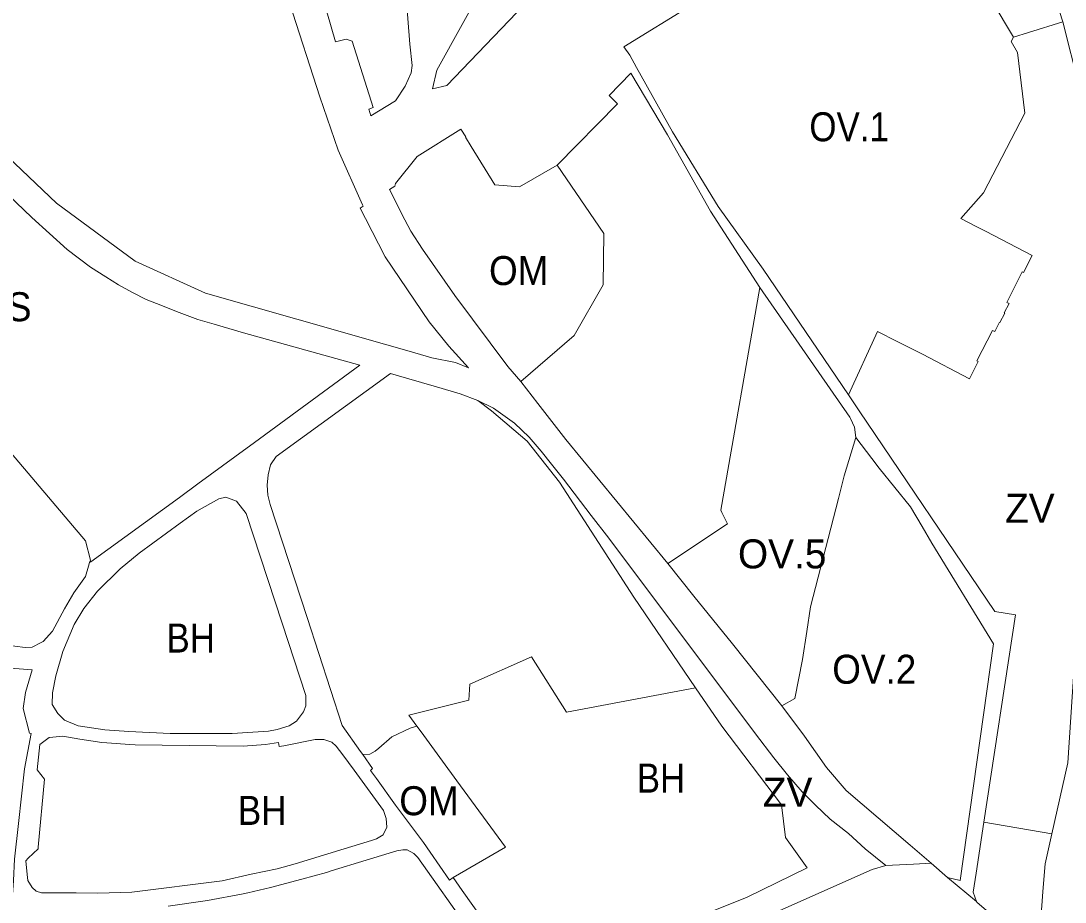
# Model space of a CAD drawing. Extents: x -650451 to -642268, y -1075216 to -1066610.
# Drawn here: x -648300.4 to -647868.5, y -1070184.8 to -1069820.3 of the extents above; entities that cross this region are included whole.
import ezdxf

# ---------------------------------------------------------------- set-up
doc = ezdxf.new("R2010")
doc.units = 0
doc.header["$LTSCALE"] = 4.8
for name, color, linetype, lineweight in [('1', 7, 'Continuous', 13), ('11', 7, 'Continuous', 13), ('12', 7, 'Continuous', 13), ('13', 7, 'Continuous', 13), ('15', 7, 'Continuous', 13), ('24', 7, 'Continuous', 13), ('25', 7, 'Continuous', 13), ('40', 7, 'Continuous', 13)]:
    doc.layers.add(name, color=color, linetype=linetype, lineweight=lineweight)
doc.layers.add('62', color=7, linetype='Continuous')

msp = doc.modelspace()

# ---------------------------------------------------------------- linework, layer by layer
at = {"layer": '1'}
for points in [[(-648395.03, -1069884.22), (-648394.65, -1069886.59), (-648395.15, -1069892.61), (-648394.35, -1069891.95), (-648373.26, -1069917.33), (-648367.49, -1069924.28), (-648364.6, -1069927.79), (-648350.48, -1069944.78), (-648341.01, -1069955.98), (-648323.69, -1069976.45), (-648316.73, -1069984.68), (-648273.67, -1070035.38), (-648271.65, -1070043.3), (-648271.95, -1070044.31)], [(-648271.95, -1070044.31), (-648271.952, -1070044.311), (-648272.42, -1070045.88), (-648273.67, -1070050.09), (-648278.48, -1070056.83), (-648282.41, -1070063.48), (-648287.34, -1070072.68), (-648291.11, -1070077.01), (-648292, -1070077.45), (-648295.66, -1070079.28), (-648298.67, -1070079.42), (-648302.91, -1070078.97), (-648311.88, -1070078.03), (-648317.52, -1070077.66), (-648327.19, -1070077.02), (-648343.29, -1070075.97), (-648350.31, -1070075.29), (-648353.76, -1070073.03), (-648359.66, -1070069.95), (-648370.54, -1070069.06), (-648388.11, -1070067.57), (-648419.45, -1070064.98), (-648446.57, -1070062.84)], [(-648136.61, -1070111.97), (-648139.91, -1070107.48), (-648115.11, -1070101.26), (-648114.7, -1070094.68), (-648089.22, -1070083.27), (-648074.76, -1070106.17), (-648021.35, -1070096.14)], [(-648021.35, -1070096.14), (-648010.55, -1070112.03), (-647985.78, -1070144.53), (-647984.1, -1070158.09), (-647975.21, -1070170.64), (-648000.23, -1070182.88), (-648016.62, -1070189.37), (-648011.68, -1070197.45)], [(-648121.6, -1070174.62), (-648099.97, -1070162.01), (-648120.06, -1070134.58), (-648125.99, -1070126.48), (-648132.7, -1070117.31), (-648133.75, -1070115.89), (-648134.45, -1070114.92), (-648136.61, -1070111.97)], [(-648239.48, -1070186.5), (-648223.26, -1070184.12), (-648208.52, -1070181.35), (-648206.53, -1070180.89), (-648197.16, -1070178.78), (-648184.18, -1070175.26), (-648174.01, -1070172.46), (-648172.09, -1070171.85), (-648157.64, -1070167.46), (-648144.96, -1070163.57), (-648142.47, -1070163.15), (-648140.61, -1070163.17), (-648137.84, -1070164.6), (-648136.17, -1070166.33), (-648114.57, -1070196.91)], [(-648011.68, -1070197.45), (-648024.97, -1070200.05), (-648029.87, -1070202.83), (-648081.95, -1070230.61), (-648084.29, -1070230.75), (-648086.84, -1070230.47), (-648089.81, -1070228.21), (-648092.22, -1070224.96), (-648097.5, -1070212.2), (-648100.3, -1070206.86), (-648104.91, -1070199.23), (-648108.41, -1070193.3), (-648117.86, -1070179.91), (-648121.6, -1070174.62)]]:
    msp.add_lwpolyline(points, dxfattribs=at)
for points in [[(-648182.51, -1070099.34), (-648182.54, -1070103.54), (-648183.54, -1070106.05), (-648186.44, -1070109.98), (-648189.4, -1070111.9), (-648194.4, -1070113.39), (-648197.98, -1070114.13), (-648212.99, -1070115.07), (-648230.77, -1070115.06), (-648233.79, -1070115), (-648238.64, -1070115), (-648255.8, -1070114.25), (-648265.64, -1070113.47), (-648276.7, -1070111.92), (-648282.33, -1070109.54), (-648285.15, -1070106.8), (-648287.42, -1070103.1), (-648287.28, -1070098.25), (-648285.93, -1070091.11), (-648283.03, -1070081.15), (-648278.31, -1070069.95), (-648274.33, -1070063.35), (-648268.73, -1070056.16), (-648259.29, -1070046.96), (-648251.42, -1070040.47), (-648234.53, -1070027.97), (-648227.66, -1070023.13), (-648218.57, -1070018.02), (-648215.61, -1070017.23), (-648211.24, -1070018.92), (-648207.15, -1070024.08), (-648192.28, -1070069.37)], [(-648150.38, -1070146.9), (-648149.31, -1070150.25), (-648149.1, -1070153.72), (-648150.59, -1070157), (-648153.26, -1070158.53), (-648155.31, -1070159.31), (-648166.7, -1070162.7), (-648186.95, -1070168.91), (-648194.4, -1070170.97), (-648205.08, -1070173.2), (-648217.18, -1070175.96), (-648254.47, -1070180.63), (-648268.56, -1070181.05), (-648277.46, -1070180.99), (-648291.84, -1070180.89), (-648294.07, -1070180.25), (-648295.72, -1070178.67), (-648297.54, -1070175.86), (-648297.81, -1070173.36), (-648298.38, -1070167.66), (-648297.44, -1070166.65), (-648293.28, -1070162.77), (-648293.22, -1070162.09), (-648290.59, -1070133.86), (-648293.6, -1070130.08), (-648292.53, -1070119.64), (-648288.71, -1070116.75), (-648284.26, -1070116.25), (-648282.99, -1070116.11), (-648275.96, -1070117.37), (-648266.95, -1070118.77), (-648264.9, -1070118.92), (-648255.26, -1070119.64), (-648253.13, -1070119.7), (-648208.45, -1070120.25), (-648199.25, -1070119.6), (-648193.81, -1070118.81), (-648193.58, -1070120.44), (-648191.62, -1070120.07), (-648178.64, -1070117.55), (-648176.49, -1070117.5), (-648175.06, -1070117.46), (-648171.75, -1070118.61), (-648169.94, -1070120.32), (-648167.26, -1070123.91), (-648162.61, -1070130.13)]]:
    msp.add_lwpolyline(points, close=True, dxfattribs=at)
at = {"layer": '11'}
for points in [[(-647958.13, -1069974.97), (-647993.37, -1069922.95), (-648011.98, -1069897.09), (-648030.85, -1069866.2), (-648045.74, -1069839.57), (-648048.56, -1069834.42), (-648051.03, -1069831.04), (-648022.75, -1069813.67), (-648017.19, -1069809.99), (-648007.72, -1069803.73), (-648002.79, -1069800.48)], [(-647898.71, -1069812.26), (-647889.83, -1069826.99)], [(-647889.83, -1069826.99), (-647890.85, -1069828.89), (-647888.27, -1069833.43), (-647885.2, -1069858.5), (-647902.22, -1069891.35), (-647911.67, -1069902.04), (-647905, -1069905.45), (-647901.47, -1069907.29), (-647882.09, -1069917.29), (-647885.73, -1069924.43), (-647886.25, -1069924.11), (-647892.61, -1069936.72), (-647891.7, -1069937.22), (-647893.68, -1069941.08), (-647893.44, -1069941.17), (-647895.45, -1069945.07), (-647895.66, -1069944.94), (-647897.64, -1069948.79), (-647898.53, -1069948.33), (-647904.96, -1069960.86), (-647904.45, -1069961.12), (-647908.08, -1069968.32), (-647927.54, -1069958.18), (-647930.53, -1069956.68), (-647937.91, -1069952.97), (-647946.07, -1069948.8), (-647958.13, -1069974.97)], [(-648032.85, -1070044.73), (-648008.18, -1070028.25), (-648010.44, -1070023.66), (-648010.94, -1070022.65), (-647994.71, -1069930.53)], [(-647994.71, -1069930.53), (-647957.59, -1069984.19), (-647957.24, -1069984.73), (-647955.65, -1069988.28), (-647955.08, -1069992.58)], [(-647955.08, -1069992.58), (-647959.84, -1070008.46), (-647962.24, -1070017.77), (-647973.82, -1070062.58), (-647975.36, -1070072.85), (-647977.13, -1070084.38), (-647980.24, -1070100.54), (-647985.64, -1070103.59)], [(-647985.64, -1070103.59), (-647980.24, -1070100.54), (-647977.13, -1070084.38), (-647975.36, -1070072.85), (-647973.82, -1070062.58), (-647962.24, -1070017.77), (-647959.84, -1070008.46), (-647955.08, -1069992.58)], [(-647955.08, -1069992.58), (-647948.506, -1070001.29), (-647948.51, -1070001.29), (-647945.48, -1070005.3), (-647932.43, -1070021.22), (-647927.6, -1070029.47), (-647923.61, -1070036.27), (-647898.15, -1070077.99), (-647911.88, -1070175.85), (-647917.1, -1070174.56), (-647923.97, -1070168.7)], [(-647985.64, -1070103.59), (-648006.05, -1070077.89), (-648022, -1070058.16), (-648032.85, -1070044.73)], [(-648379.47, -1070082.24), (-648375.71, -1070082.53), (-648358.72, -1070083.83), (-648295.75, -1070088.68), (-648298.44, -1070098.07), (-648299.4, -1070104.67), (-648296.81, -1070114.95), (-648296.09, -1070115.09), (-648298.93, -1070129.7), (-648301.38, -1070152.29), (-648302.98, -1070166.99), (-648303.45, -1070175.81), (-648304.71, -1070193.48), (-648305, -1070203.13), (-648305.26, -1070208.56)], [(-647923.97, -1070168.7), (-647932.63, -1070161.19), (-647959.1, -1070138.59), (-647967.22, -1070129.11), (-647976.36, -1070116.1), (-647985.64, -1070103.59)]]:
    msp.add_lwpolyline(points, dxfattribs=at)
at = {"layer": '12'}
for points in [[(-648093.67, -1069969.42), (-648099.05, -1069963.26), (-648120.85, -1069933.91), (-648134.34, -1069914.68), (-648139.17, -1069907.27), (-648142.86, -1069900.24), (-648147.27, -1069891.3), (-648147.87, -1069890.04), (-648145.73, -1069888.68), (-648145.5, -1069887.55), (-648136.5, -1069876.35), (-648118.4, -1069865.04), (-648116.39, -1069868.28), (-648116.48, -1069868.33), (-648114.11, -1069872.2), (-648104.4, -1069888.09), (-648094.2, -1069888.93), (-648078.54, -1069880.01)], [(-648078.54, -1069880.01), (-648059.32, -1069908.27), (-648059.5, -1069929.52), (-648071.58, -1069950.39), (-648093.67, -1069969.42)], [(-648159.02, -1070123.71), (-648156.07, -1070123.54), (-648153.85, -1070122.38), (-648152.35, -1070121.05), (-648147.02, -1070116.35), (-648139.45, -1070112.79), (-648136.61, -1070111.97)], [(-648136.61, -1070111.97), (-648134.45, -1070114.92), (-648133.75, -1070115.89), (-648132.7, -1070117.31), (-648125.99, -1070126.48), (-648120.06, -1070134.58), (-648099.97, -1070162.01), (-648121.6, -1070174.62)], [(-648121.6, -1070174.62), (-648123.08, -1070175.66), (-648131.16, -1070164.06), (-648133.91, -1070160.15), (-648145.41, -1070144.66), (-648153.3, -1070133.69), (-648155.78, -1070130.27), (-648154.95, -1070129.55), (-648159.02, -1070123.71)]]:
    msp.add_lwpolyline(points, dxfattribs=at)
at = {"layer": '13'}
msp.add_lwpolyline([(-648141.17, -1069808.61), (-648139.49, -1069829.91), (-648138.57, -1069838.78), (-648138.96, -1069841.84), (-648141.51, -1069847.31), (-648145.49, -1069853.38), (-648155.65, -1069859.62), (-648156.51, -1069856.79), (-648154.66, -1069856.18), (-648163.33, -1069828.65), (-648165.79, -1069827.8), (-648170.31, -1069828.95), (-648187.37, -1069769.73)], dxfattribs=at)
at = {"layer": '15'}
for points in [[(-648077.36, -1069748.57), (-648128.33, -1069840.75), (-648130.16, -1069848.43), (-648124.28, -1069847.04), (-648050.23, -1069769.71)], [(-648187.37, -1069769.73), (-648170.31, -1069828.95), (-648165.79, -1069827.8), (-648163.33, -1069828.65), (-648154.66, -1069856.18), (-648156.51, -1069856.79), (-648155.65, -1069859.62), (-648145.49, -1069853.38), (-648141.51, -1069847.31), (-648138.96, -1069841.84), (-648138.57, -1069838.78), (-648139.49, -1069829.91), (-648141.17, -1069808.61)], [(-648160.04, -1069897.73), (-648158.79, -1069896.95), (-648159.1, -1069896.39), (-648169.15, -1069873.81), (-648176.78, -1069851.74), (-648201.83, -1069773.86)], [(-647886.49, -1069778.43), (-647883.51, -1069783.05), (-647879.63, -1069789.06), (-647877.49, -1069795.99), (-647870.84, -1069816.36), (-647869.45, -1069820.63)], [(-648002.79, -1069800.48), (-648007.72, -1069803.73), (-648017.19, -1069809.99), (-648022.75, -1069813.67), (-648051.03, -1069831.04), (-648048.56, -1069834.42), (-648045.74, -1069839.57), (-648030.85, -1069866.2), (-648011.98, -1069897.09), (-647993.37, -1069922.95), (-647958.13, -1069974.97)], [(-647869.45, -1069820.63), (-647883.66, -1069825.06), (-647889.83, -1069826.99), (-647898.71, -1069812.26)], [(-648363.68, -1069819.31), (-648365.81, -1069819.9), (-648340.38, -1069843.78), (-648285.62, -1069895.71), (-648253.13, -1069919.7), (-648223.99, -1069932.96), (-648186.268, -1069943.697), (-648150.006, -1069954.019)], [(-647994.71, -1069930.53), (-648015.11, -1069898.98), (-648032.94, -1069867.46), (-648048.08, -1069841.95), (-648057.11, -1069851.12), (-648053.61, -1069854.64), (-648078.54, -1069880.01)], [(-648078.54, -1069880.01), (-648094.2, -1069888.93), (-648104.4, -1069888.09), (-648114.11, -1069872.2), (-648116.48, -1069868.33), (-648116.39, -1069868.28), (-648118.4, -1069865.04), (-648136.5, -1069876.35), (-648145.5, -1069887.55), (-648145.73, -1069888.68), (-648147.87, -1069890.04), (-648147.27, -1069891.3), (-648142.86, -1069900.24), (-648139.17, -1069907.27), (-648134.34, -1069914.68), (-648120.85, -1069933.91), (-648099.05, -1069963.26), (-648093.67, -1069969.42)], [(-648271.95, -1070044.31), (-648271.5, -1070043.98), (-648234.79, -1070017.36), (-648227.16, -1070011.83), (-648206.77, -1069996.87), (-648205.77, -1069996.14), (-648160.27, -1069962.63), (-648208.27, -1069949.26), (-648214.42, -1069947.46), (-648220.42, -1069945.7), (-648227.23, -1069943.8), (-648236.06, -1069940.52), (-648242.53, -1069937.92), (-648248.62, -1069935.54), (-648254.18, -1069932.68), (-648260.08, -1069929.44), (-648265.24, -1069926.2), (-648271.62, -1069922.1), (-648281.22, -1069914.79), (-648295.88, -1069901.64), (-648318.63, -1069879.94)], [(-648149.67, -1069917.83), (-648157.81, -1069902.06), (-648160.04, -1069897.73)], [(-648150.006, -1069954.019), (-648139.78, -1069956.93), (-648130.36, -1069959.62), (-648120.68, -1069961.63), (-648115.23, -1069963.75), (-648123.45, -1069954.79), (-648131.5, -1069944.75), (-648149.67, -1069917.83)], [(-647955.08, -1069992.58), (-647955.65, -1069988.28), (-647957.24, -1069984.73), (-647957.59, -1069984.19), (-647994.71, -1069930.53)], [(-648111.44, -1069977.32), (-648118.75, -1069974.53), (-648128.48, -1069971.7), (-648140.96, -1069968.01), (-648147.46, -1069966.19), (-648194.84, -1070000.49), (-648197.19, -1070003.94), (-648198.17, -1070008.05), (-648198.48, -1070012.3), (-648198.22, -1070016.4), (-648197.23, -1070020.37), (-648182.01, -1070067.11), (-648167.48, -1070111.75), (-648159.89, -1070122.49), (-648159.02, -1070123.71)], [(-648093.67, -1069969.42), (-648086.55, -1069978.57), (-648074.96, -1069993.46), (-648032.85, -1070044.73)], [(-647958.13, -1069974.97), (-647953.67, -1069981.55), (-647897.53, -1070064.61), (-647889.09, -1070065.99), (-647902.17, -1070151.64)], [(-647942.7, -1070169.68), (-647951.22, -1070162.74), (-647958.07, -1070156.4), (-647965.73, -1070150.45), (-647971.79, -1070144.72), (-647977.25, -1070139.17), (-647983.34, -1070132.09), (-647989.01, -1070125.06), (-647996.59, -1070115.11), (-648057.18, -1070034.29), (-648064.48, -1070024.93), (-648076.04, -1070009.81), (-648080.91, -1070003.62), (-648085.16, -1069998.26), (-648090.23, -1069992.48), (-648096.28, -1069986.67), (-648104.91, -1069980.46), (-648111.44, -1069977.32)], [(-647917.1, -1070174.56), (-647911.88, -1070175.85), (-647898.15, -1070077.99), (-647923.61, -1070036.27), (-647927.6, -1070029.47), (-647932.43, -1070021.22), (-647945.48, -1070005.3), (-647948.51, -1070001.29), (-647948.506, -1070001.29), (-647955.08, -1069992.58)], [(-648446.57, -1070062.84), (-648419.45, -1070064.98), (-648388.11, -1070067.57), (-648370.54, -1070069.06), (-648359.66, -1070069.95), (-648353.76, -1070073.03), (-648350.31, -1070075.29), (-648343.29, -1070075.97), (-648327.19, -1070077.02), (-648317.52, -1070077.66), (-648311.88, -1070078.03), (-648302.91, -1070078.97), (-648298.67, -1070079.42), (-648295.66, -1070079.28), (-648292, -1070077.45), (-648291.11, -1070077.01), (-648287.34, -1070072.68), (-648282.41, -1070063.48), (-648278.48, -1070056.83), (-648273.67, -1070050.09), (-648272.42, -1070045.88), (-648271.952, -1070044.311), (-648271.95, -1070044.31)], [(-648032.85, -1070044.73), (-648022, -1070058.16), (-648006.05, -1070077.89), (-647985.64, -1070103.59)], [(-648305.26, -1070208.56), (-648305, -1070203.13), (-648304.71, -1070193.48), (-648303.45, -1070175.81), (-648302.98, -1070166.99), (-648301.38, -1070152.29), (-648298.93, -1070129.7), (-648296.09, -1070115.09), (-648296.81, -1070114.95), (-648299.4, -1070104.67), (-648298.44, -1070098.07), (-648295.75, -1070088.68), (-648358.72, -1070083.83), (-648375.71, -1070082.53), (-648379.47, -1070082.24)], [(-647985.64, -1070103.59), (-647976.36, -1070116.1), (-647967.22, -1070129.11), (-647959.1, -1070138.59), (-647932.63, -1070161.19), (-647923.97, -1070168.7)], [(-648159.02, -1070123.71), (-648154.95, -1070129.55), (-648155.78, -1070130.27), (-648153.3, -1070133.69), (-648145.41, -1070144.66), (-648133.91, -1070160.15), (-648131.16, -1070164.06), (-648123.08, -1070175.66), (-648121.6, -1070174.62)], [(-647902.17, -1070151.64), (-647905.28, -1070172.86), (-647906.6, -1070180.65), (-647905.17, -1070184.5), (-647917.1, -1070174.56)], [(-648114.57, -1070196.91), (-648136.17, -1070166.33), (-648137.84, -1070164.6), (-648140.61, -1070163.17), (-648142.47, -1070163.15), (-648144.96, -1070163.57), (-648157.64, -1070167.46), (-648172.09, -1070171.85), (-648174.01, -1070172.46), (-648184.18, -1070175.26), (-648197.16, -1070178.78), (-648206.53, -1070180.89), (-648208.52, -1070181.35), (-648223.26, -1070184.12), (-648239.48, -1070186.5)], [(-647923.97, -1070168.7), (-647931.25, -1070169.08), (-647939.95, -1070169.53), (-647942.7, -1070169.68)], [(-648121.6, -1070174.62), (-648117.86, -1070179.91), (-648108.41, -1070193.3), (-648104.91, -1070199.23), (-648100.3, -1070206.86), (-648097.5, -1070212.2), (-648092.22, -1070224.96), (-648089.81, -1070228.21), (-648086.84, -1070230.47), (-648084.29, -1070230.75), (-648081.95, -1070230.61), (-648029.87, -1070202.83), (-648024.97, -1070200.05), (-648011.68, -1070197.45), (-648003.88, -1070195.93)]]:
    msp.add_lwpolyline(points, dxfattribs=at)
for points in [[(-648182.51, -1070099.34), (-648192.28, -1070069.37), (-648207.15, -1070024.08), (-648211.24, -1070018.92), (-648215.61, -1070017.23), (-648218.57, -1070018.02), (-648227.66, -1070023.13), (-648234.53, -1070027.97), (-648251.42, -1070040.47), (-648259.29, -1070046.96), (-648268.73, -1070056.16), (-648274.33, -1070063.35), (-648278.31, -1070069.95), (-648283.03, -1070081.15), (-648285.93, -1070091.11), (-648287.28, -1070098.25), (-648287.42, -1070103.1), (-648285.15, -1070106.8), (-648282.33, -1070109.54), (-648276.7, -1070111.92), (-648265.64, -1070113.47), (-648255.8, -1070114.25), (-648238.64, -1070115), (-648233.79, -1070115), (-648230.77, -1070115.06), (-648212.99, -1070115.07), (-648197.98, -1070114.13), (-648194.4, -1070113.39), (-648189.4, -1070111.9), (-648186.44, -1070109.98), (-648183.54, -1070106.05), (-648182.54, -1070103.54)], [(-648150.38, -1070146.9), (-648162.61, -1070130.13), (-648167.26, -1070123.91), (-648169.94, -1070120.32), (-648171.75, -1070118.61), (-648175.06, -1070117.46), (-648176.49, -1070117.5), (-648178.64, -1070117.55), (-648191.62, -1070120.07), (-648193.58, -1070120.44), (-648193.81, -1070118.81), (-648199.25, -1070119.6), (-648208.45, -1070120.25), (-648253.13, -1070119.7), (-648255.26, -1070119.64), (-648264.9, -1070118.92), (-648266.95, -1070118.77), (-648275.96, -1070117.37), (-648282.99, -1070116.11), (-648284.26, -1070116.25), (-648288.71, -1070116.75), (-648292.53, -1070119.64), (-648293.6, -1070130.08), (-648290.59, -1070133.86), (-648293.22, -1070162.09), (-648293.28, -1070162.77), (-648297.44, -1070166.65), (-648298.38, -1070167.66), (-648297.81, -1070173.36), (-648297.54, -1070175.86), (-648295.72, -1070178.67), (-648294.07, -1070180.25), (-648291.84, -1070180.89), (-648277.46, -1070180.99), (-648268.56, -1070181.05), (-648254.47, -1070180.63), (-648217.18, -1070175.96), (-648205.08, -1070173.2), (-648194.4, -1070170.97), (-648186.95, -1070168.91), (-648166.7, -1070162.7), (-648155.31, -1070159.31), (-648153.26, -1070158.53), (-648150.59, -1070157), (-648149.1, -1070153.72), (-648149.31, -1070150.25)]]:
    msp.add_lwpolyline(points, close=True, dxfattribs=at)
at = {"layer": '24'}
for points in [[(-648318.63, -1069879.94), (-648295.88, -1069901.64), (-648281.22, -1069914.79), (-648271.62, -1069922.1), (-648265.24, -1069926.2), (-648260.08, -1069929.44), (-648254.18, -1069932.68), (-648248.62, -1069935.54), (-648242.53, -1069937.92), (-648236.06, -1069940.52), (-648227.23, -1069943.8), (-648220.42, -1069945.7), (-648214.42, -1069947.46), (-648208.27, -1069949.26), (-648160.27, -1069962.63), (-648205.77, -1069996.14), (-648206.77, -1069996.87), (-648227.16, -1070011.83), (-648234.79, -1070017.36), (-648271.5, -1070043.98), (-648271.95, -1070044.31)], [(-648271.95, -1070044.31), (-648271.65, -1070043.3), (-648273.67, -1070035.38), (-648316.73, -1069984.68), (-648323.69, -1069976.45), (-648341.01, -1069955.98), (-648350.48, -1069944.78), (-648364.6, -1069927.79), (-648367.49, -1069924.28), (-648373.26, -1069917.33), (-648394.35, -1069891.95), (-648395.15, -1069892.61), (-648394.65, -1069886.59), (-648395.03, -1069884.22)], [(-647942.7, -1070169.68), (-647939.95, -1070169.53), (-647931.25, -1070169.08), (-647923.97, -1070168.7), (-647917.1, -1070174.56), (-647905.17, -1070184.5)], [(-648003.88, -1070195.93), (-647948.25, -1070171.21), (-647942.7, -1070169.68)], [(-647905.17, -1070184.5), (-647905.08, -1070184.73), (-647879.839, -1070206.461)]]:
    msp.add_lwpolyline(points, dxfattribs=at)
at = {"layer": '25'}
for points in [[(-647869.45, -1069820.63), (-647870.84, -1069816.36), (-647877.49, -1069795.99), (-647879.63, -1069789.06), (-647883.51, -1069783.05), (-647886.49, -1069778.43), (-647947.59, -1069683.79)], [(-647873.97, -1070156.58), (-647867.36, -1070127.21), (-647863.6, -1070070.49), (-647860.76, -1070027.86), (-647859.17, -1070011.72), (-647865.08, -1070001.86), (-647861.12, -1069970.21), (-647860.25, -1069956.63), (-647858.77, -1069940.78), (-647857.31, -1069921.08), (-647858.4, -1069889.05), (-647862.05, -1069861.48), (-647862.69, -1069856.72), (-647862.69, -1069847.43), (-647869.45, -1069820.63)], [(-647879.839, -1070206.461), (-647879.81, -1070206.08), (-647878.18, -1070186.33), (-647877.68, -1070180.34), (-647876.74, -1070168.88), (-647873.97, -1070156.58)]]:
    msp.add_lwpolyline(points, dxfattribs=at)
at = {"layer": '40'}
for points in [[(-648050.23, -1069769.71), (-648124.28, -1069847.04), (-648130.16, -1069848.43), (-648128.33, -1069840.75), (-648077.36, -1069748.57)], [(-647869.45, -1069820.63), (-647862.69, -1069847.43), (-647862.69, -1069856.72), (-647862.05, -1069861.48), (-647858.4, -1069889.05), (-647857.31, -1069921.08), (-647858.77, -1069940.78), (-647860.25, -1069956.63), (-647861.12, -1069970.21), (-647865.08, -1070001.86), (-647859.17, -1070011.72), (-647860.76, -1070027.86), (-647863.6, -1070070.49), (-647867.36, -1070127.21), (-647873.97, -1070156.58), (-647902.17, -1070151.64)], [(-647889.83, -1069826.99), (-647883.66, -1069825.06), (-647869.45, -1069820.63)], [(-647958.13, -1069974.97), (-647946.07, -1069948.8), (-647937.91, -1069952.97), (-647930.53, -1069956.68), (-647927.54, -1069958.18), (-647908.08, -1069968.32), (-647904.45, -1069961.12), (-647904.96, -1069960.86), (-647898.53, -1069948.33), (-647897.64, -1069948.79), (-647895.66, -1069944.94), (-647895.45, -1069945.07), (-647893.44, -1069941.17), (-647893.68, -1069941.08), (-647891.7, -1069937.22), (-647892.61, -1069936.72), (-647886.25, -1069924.11), (-647885.73, -1069924.43), (-647882.09, -1069917.29), (-647901.47, -1069907.29), (-647905, -1069905.45), (-647911.67, -1069902.04), (-647902.22, -1069891.35), (-647885.2, -1069858.5), (-647888.27, -1069833.43), (-647890.85, -1069828.89), (-647889.83, -1069826.99)], [(-647902.17, -1070151.64), (-647889.09, -1070065.99), (-647897.53, -1070064.61), (-647953.67, -1069981.55), (-647958.13, -1069974.97)], [(-648111.44, -1069977.32), (-648104.91, -1069980.46), (-648096.28, -1069986.67), (-648090.23, -1069992.48), (-648085.16, -1069998.26), (-648080.91, -1070003.62), (-648076.04, -1070009.81), (-648064.48, -1070024.93), (-648057.18, -1070034.29), (-647996.59, -1070115.11), (-647989.01, -1070125.06), (-647983.34, -1070132.09), (-647977.25, -1070139.17), (-647971.79, -1070144.72), (-647965.73, -1070150.45), (-647958.07, -1070156.4), (-647951.22, -1070162.74), (-647942.7, -1070169.68)], [(-648021.35, -1070096.14), (-648046.83, -1070058.62), (-648077.68, -1070011.06), (-648091.06, -1069994.07), (-648105.79, -1069981.56), (-648111.44, -1069977.32)], [(-648011.68, -1070197.45), (-648016.62, -1070189.37), (-648000.23, -1070182.88), (-647975.21, -1070170.64), (-647984.1, -1070158.09), (-647985.78, -1070144.53), (-648010.55, -1070112.03), (-648021.35, -1070096.14)], [(-647942.7, -1070169.68), (-647948.25, -1070171.21), (-648003.88, -1070195.93), (-648011.68, -1070197.45)]]:
    msp.add_lwpolyline(points, dxfattribs=at)

# ---------------------------------------------------------------- texts
at = {"layer": '62'}
for s, width, p in [('OV.1', 0.9, (-647974.294, -1069870.096)), ('OM', 0.95, (-648106.772, -1069929.564)), ('DS', 0.95, (-648317.157, -1069944.523)), ('BH', 0.9, (-648240.174, -1070081.551)), ('OV.2', 0.95, (-647964.818, -1070094.452)), ('BH', 0.9, (-648045.677, -1070139.484)), ('OM', 0.95, (-648143.88, -1070148.836)), ('BH', 0.9, (-648210.621, -1070152.845))]:
    msp.add_text(s, height=12, dxfattribs=dict(at, width=width)).set_placement(p)
for s, p in [('ZV', (-647893.358, -1070027.892)), ('OV.5', (-648003.819, -1070046.742)), ('ZV', (-647993.532, -1070145.329))]:
    msp.add_text(s, height=12, dxfattribs=at).set_placement(p)

doc.saveas('drawing.dxf')
